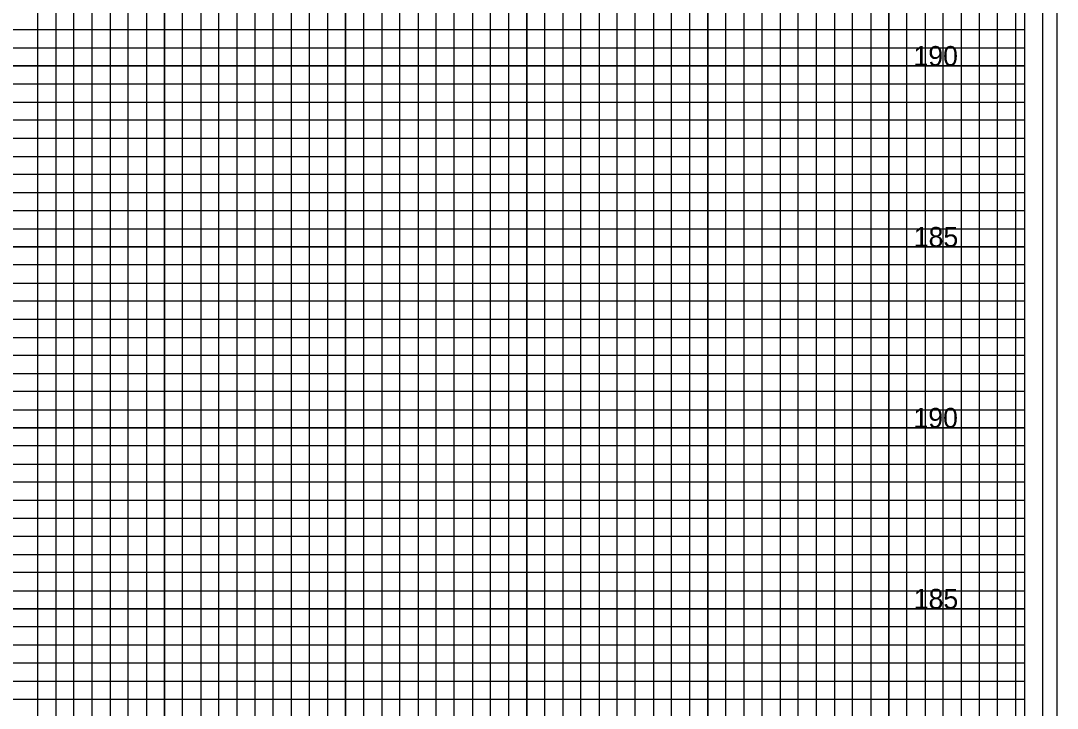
# Model space of a CAD drawing. Extents: x -4 to 103, y -2 to 67.
# Drawn here: x 74.78 to 103.4, y 32.25 to 51.25 of the extents above; entities that cross this region are included whole.
import ezdxf

# ---------------------------------------------------------------- set-up
doc = ezdxf.new("R2010")
doc.units = 0
for name, color, linetype in [('Exist XS Ground Line', 7, 'Continuous'), ('Old_Level_10', 7, 'Continuous'), ('Old_Level_4', 7, 'Continuous'), ('Old_Level_5', 7, 'Continuous'), ('Old_Level_8', 7, 'Continuous'), ('Prop XS Elevation Labels', 7, 'Continuous'), ('Prop XS Finish Grade Concrete', 7, 'Continuous')]:
    doc.layers.add(name, color=color, linetype=linetype)

msp = doc.modelspace()

# ---------------------------------------------------------------- linework, layer by layer
at = {"layer": 'Exist XS Ground Line'}
msp.add_lwpolyline([(102.5, 65), (0, 65), (0, 0), (102.5, 0)], close=True, dxfattribs=at)
at = {"layer": 'Old_Level_10'}
for p, q in [((91.25, 0), (91.25, 63.425)), ((93.75, 0), (93.75, 63.425)), ((96.25, 0), (96.25, 63.425)), ((98.75, 0), (98.75, 63.425)), ((101.25, 0), (101.25, 63.425)), ((76.25, 0), (76.25, 62)), ((78.75, 0), (78.75, 62)), ((81.25, 0), (81.25, 62)), ((83.75, 0), (83.75, 62)), ((86.25, 0), (86.25, 62)), ((88.75, 0), (88.75, 62)), ((0, 50), (102.5, 50)), ((0, 47.5), (102.5, 47.5)), ((0, 45), (102.5, 45)), ((0, 42.5), (102.5, 42.5)), ((0, 40), (102.5, 40)), ((0, 37.5), (102.5, 37.5)), ((0, 35), (102.5, 35)), ((0, 32.5), (102.5, 32.5))]:
    msp.add_line(p, q, dxfattribs=at)
at = {"layer": 'Old_Level_4'}
msp.add_lwpolyline([(103, 66), (-2.8, 66), (-2.8, -1), (103, -1)], close=True, dxfattribs=at)
at = {"layer": 'Old_Level_5'}
msp.add_lwpolyline([(103.4, 67.4), (-3.5, 67.4), (-3.5, -2.425), (103.4, -2.425)], close=True, dxfattribs=at)
at = {"layer": 'Old_Level_8'}
for points in [[(91.25, 0), (91.25, 63.425), (93.75, 63.425), (93.75, 0)], [(96.25, 0), (96.25, 63.425), (98.75, 63.425), (98.75, 0)], [(101.25, 0), (101.25, 63.425)], [(76.25, 0), (76.25, 62), (78.75, 62), (78.75, 0)], [(81.25, 0), (81.25, 62), (83.75, 62), (83.75, 0)], [(86.25, 0), (86.25, 62), (88.75, 62), (88.75, 0)], [(0, 47.5), (102.5, 47.5), (102.5, 50), (0, 50)], [(0, 42.5), (102.5, 42.5), (102.5, 45), (0, 45)], [(0, 37.5), (102.5, 37.5), (102.5, 40), (0, 40)], [(0, 32.5), (102.5, 32.5), (102.5, 35), (0, 35)]]:
    msp.add_lwpolyline(points, dxfattribs=at)
at = {"layer": 'Prop XS Elevation Labels'}
for points in [[(90.25, 0), (90.25, 63.425), (90.75, 63.425), (90.75, 0)], [(91.75, 0), (91.75, 63.425), (92.25, 63.425), (92.25, 0)], [(92.75, 0), (92.75, 63.425), (93.25, 63.425), (93.25, 0)], [(94.25, 0), (94.25, 63.425), (94.75, 63.425), (94.75, 0)], [(95.25, 0), (95.25, 63.425), (95.75, 63.425), (95.75, 0)], [(96.75, 0), (96.75, 63.425), (97.25, 63.425), (97.25, 0)], [(97.75, 0), (97.75, 63.425), (98.25, 63.425), (98.25, 0)], [(99.25, 0), (99.25, 63.425), (99.75, 63.425), (99.75, 0)], [(100.25, 0), (100.25, 63.425)], [(100.25, 63.425), (100.75, 63.425), (100.75, 0), (101.75, 0), (101.75, 63.425), (102.25, 63.425), (102.25, 0)], [(75.25, 0), (75.25, 62), (75.75, 62), (75.75, 0)], [(76.75, 0), (76.75, 62), (77.25, 62), (77.25, 0)], [(77.75, 0), (77.75, 62), (78.25, 62), (78.25, 0)], [(79.25, 0), (79.25, 62), (79.75, 62), (79.75, 0)], [(80.25, 0), (80.25, 62), (80.75, 62), (80.75, 0)], [(81.75, 0), (81.75, 62), (82.25, 62), (82.25, 0)], [(82.75, 0), (82.75, 62), (83.25, 62), (83.25, 0)], [(84.25, 0), (84.25, 62), (84.75, 62), (84.75, 0)], [(85.25, 0), (85.25, 62), (85.75, 62), (85.75, 0)], [(86.75, 0), (86.75, 62), (87.25, 62), (87.25, 0)], [(87.75, 0), (87.75, 62), (88.25, 62), (88.25, 0)], [(89.25, 0), (89.25, 62), (89.75, 62), (89.75, 0)], [(0, 50.5), (102.5, 50.5), (102.5, 51), (0, 51)], [(0, 49), (102.5, 49), (102.5, 49.5), (0, 49.5)], [(0, 48), (102.5, 48), (102.5, 48.5), (0, 48.5)], [(0, 46.5), (102.5, 46.5), (102.5, 47), (0, 47)], [(0, 45.5), (102.5, 45.5), (102.5, 46), (0, 46)], [(0, 44), (102.5, 44), (102.5, 44.5), (0, 44.5)], [(0, 43), (102.5, 43), (102.5, 43.5), (0, 43.5)], [(0, 41.5), (102.5, 41.5), (102.5, 42), (0, 42)], [(0, 40.5), (102.5, 40.5), (102.5, 41), (0, 41)], [(0, 39), (102.5, 39), (102.5, 39.5), (0, 39.5)], [(0, 38), (102.5, 38), (102.5, 38.5), (0, 38.5)], [(0, 36.5), (102.5, 36.5), (102.5, 37), (0, 37)], [(0, 35.5), (102.5, 35.5), (102.5, 36), (0, 36)], [(0, 34), (102.5, 34), (102.5, 34.5), (0, 34.5)], [(0, 33), (102.5, 33), (102.5, 33.5), (0, 33.5)]]:
    msp.add_lwpolyline(points, dxfattribs=at)

# ---------------------------------------------------------------- texts
at = {"layer": 'Prop XS Finish Grade Concrete'}
for s, p in [('190', (99.4296, 50)), ('185', (99.4383, 45)), ('190', (99.4296, 40)), ('185', (99.4383, 35))]:
    msp.add_text(s, height=0.55, dxfattribs=at).set_placement(p)

doc.saveas('drawing.dxf')
